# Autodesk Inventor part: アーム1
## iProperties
Created: 2008-02
Part Number: アーム1
Document SubType Name: Modeling
Designer: y-shimazaki
Density: 1 g/cm^3
Author: y-shimazaki
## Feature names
1. 押し出し1 [Extrusion]
2. 押し出し2 [Extrusion]
3. 穴1 [Hole]
4. 面取り1 [Chamfer]
5. フィレット1 [Fillet]
